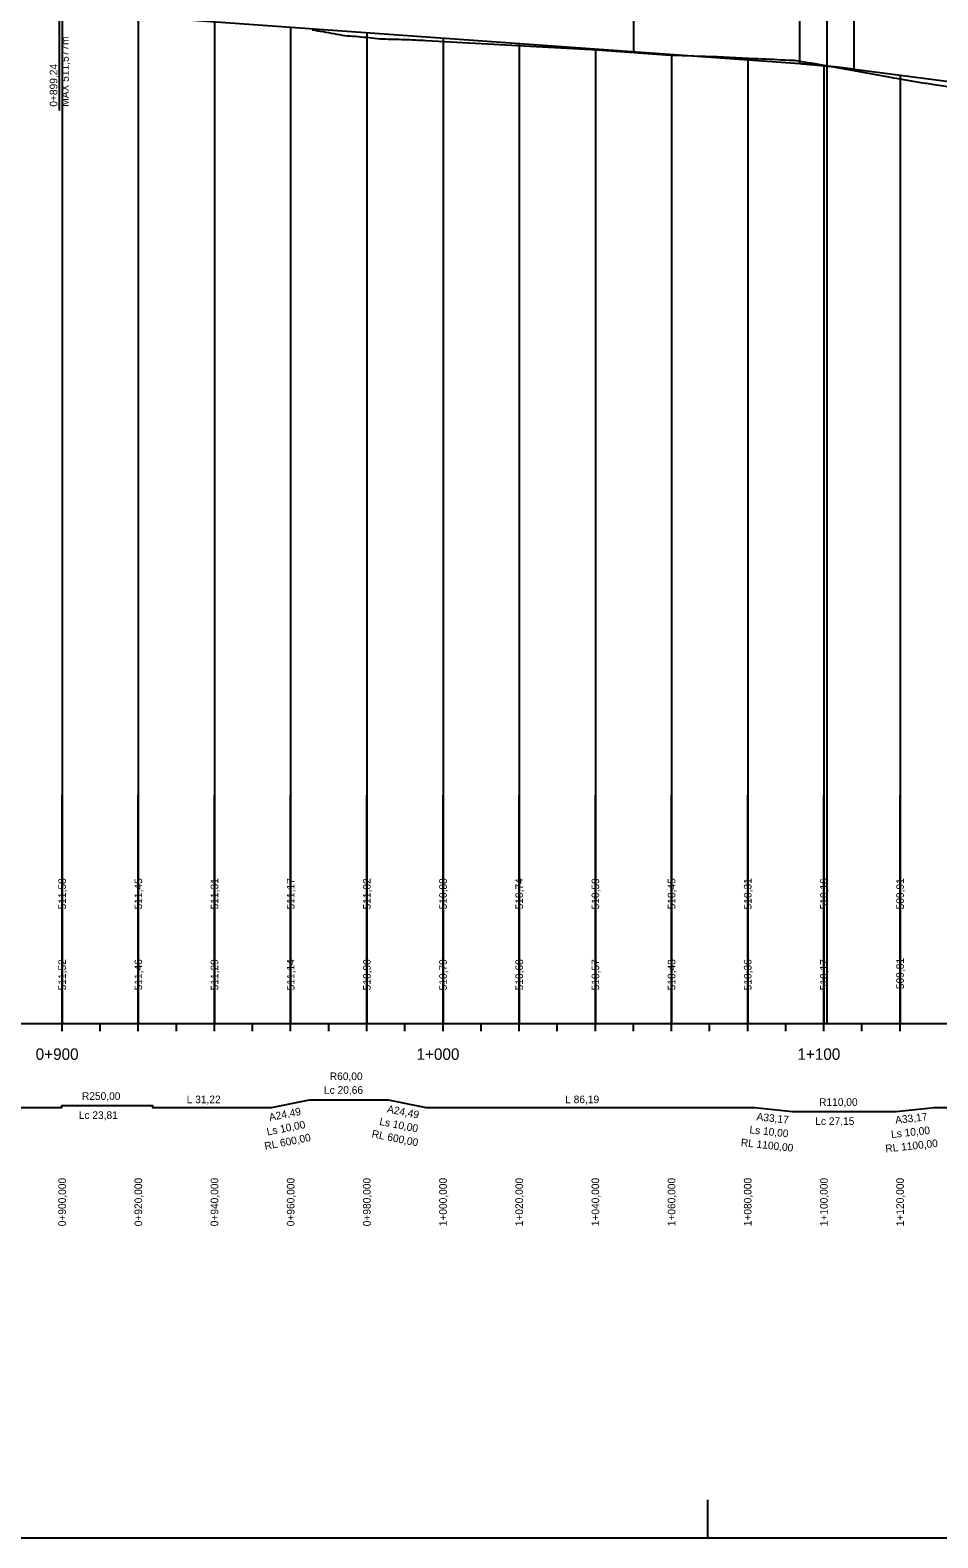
# Model space of a CAD drawing. Extents: x -632716 to -629545, y -1094726 to -1088285.
# Drawn here: x -631637 to -631398.7, y -1091981 to -1091585.1 of the extents above; entities that cross this region are included whole.
import ezdxf

# ---------------------------------------------------------------- set-up
doc = ezdxf.new("R2010")
doc.units = 0
for name, color, linetype in [('20', 7, 'Continuous'), ('Default', 7, 'Continuous'), ('formát', 7, 'Continuous'), ('NIVELETA_VYSKY', 7, 'Continuous'), ('REZ_POPIS', 7, 'Continuous'), ('REZ_TABULKA', 7, 'Continuous'), ('REZ_TENKA', 7, 'Continuous'), ('REZ_TLUSTA', 7, 'Continuous'), ('SKLONY_NIVELETA', 7, 'Continuous'), ('SKLONY_POPIS', 7, 'Continuous'), ('TECNY_NIVELETA', 7, 'Continuous'), ('TEREN_VYSKY', 7, 'Continuous'), ('VOZOVKA', 7, 'Continuous')]:
    doc.layers.add(name, color=color, linetype=linetype)

msp = doc.modelspace()

# ---------------------------------------------------------------- linework, layer by layer
at = {"layer": '20'}
for points in [[(-631628.64, -1091580.23), (-631628.64, -1091795.99), (-631628.64, -1091845.99), (-631628.64, -1091785.99)], [(-631608.64, -1091581.46), (-631608.64, -1091795.99), (-631608.64, -1091845.99), (-631608.64, -1091785.99)], [(-631588.64, -1091582.89), (-631588.64, -1091795.99), (-631588.64, -1091845.99), (-631588.64, -1091785.99)], [(-631568.64, -1091584.32), (-631568.64, -1091795.99), (-631568.64, -1091845.99), (-631568.64, -1091785.99)], [(-631548.64, -1091585.76), (-631548.64, -1091795.99), (-631548.64, -1091845.99), (-631548.64, -1091785.99)], [(-631528.64, -1091587.19), (-631528.64, -1091795.99), (-631528.64, -1091845.99), (-631528.64, -1091785.99)], [(-631508.64, -1091588.62), (-631508.64, -1091795.99), (-631508.64, -1091845.99), (-631508.64, -1091785.99)], [(-631488.64, -1091590.05), (-631488.64, -1091795.99), (-631488.64, -1091845.99), (-631488.64, -1091785.99)], [(-631468.64, -1091591.48), (-631468.64, -1091795.99), (-631468.64, -1091845.99), (-631468.64, -1091785.99)], [(-631448.64, -1091592.91), (-631448.64, -1091795.99), (-631448.64, -1091845.99), (-631448.64, -1091785.99)], [(-631428.64, -1091594.43), (-631428.64, -1091795.99), (-631428.64, -1091845.99), (-631428.64, -1091785.99)], [(-631408.64, -1091596.9), (-631408.64, -1091795.99), (-631408.64, -1091845.99), (-631408.64, -1091785.99)]]:
    msp.add_lwpolyline(points, dxfattribs=at)
at = {"layer": 'Default'}
for p, q in [((-631622.48, -1091580.47), (-631434.99, -1091593.89)), ((-631420.67, -1091595.33), (-631303.16, -1091610.61))]:
    msp.add_line(p, q, dxfattribs=at)
msp.add_lwpolyline([(-631434.99, -1091593.89), (-631434.69, -1091593.91), (-631434.39, -1091593.93), (-631434.1, -1091593.96), (-631433.8, -1091593.98), (-631433.5, -1091594), (-631433.2, -1091594.03), (-631432.9, -1091594.05), (-631432.6, -1091594.07), (-631432.3, -1091594.1), (-631432.01, -1091594.12), (-631431.71, -1091594.15), (-631431.41, -1091594.17), (-631431.11, -1091594.2), (-631430.81, -1091594.23), (-631430.51, -1091594.25), (-631430.22, -1091594.28), (-631429.92, -1091594.31), (-631429.62, -1091594.33), (-631429.32, -1091594.36), (-631429.02, -1091594.39), (-631428.72, -1091594.42), (-631428.43, -1091594.45), (-631428.13, -1091594.48), (-631427.53, -1091594.54), (-631427.23, -1091594.57), (-631426.93, -1091594.6), (-631426.64, -1091594.63), (-631426.34, -1091594.66), (-631426.04, -1091594.7), (-631425.74, -1091594.73), (-631425.44, -1091594.76), (-631425.14, -1091594.79), (-631424.85, -1091594.83), (-631424.55, -1091594.86), (-631424.25, -1091594.9), (-631423.95, -1091594.93), (-631423.65, -1091594.96), (-631423.35, -1091595), (-631423.06, -1091595.04), (-631422.76, -1091595.07), (-631422.46, -1091595.11), (-631422.16, -1091595.15), (-631421.86, -1091595.18), (-631421.56, -1091595.22), (-631421.27, -1091595.26), (-631420.97, -1091595.3), (-631420.67, -1091595.33)], dxfattribs=at)
at = {"layer": 'formát'}
msp.add_line((-631459.11, -1091981.01), (-631459.11, -1091971.01), dxfattribs=at)
msp.add_lwpolyline([(-632628.81, -1091981.01), (-629779.11, -1091981.01), (-629779.11, -1091387.01), (-632628.81, -1091387.01)], close=True, dxfattribs=at)
at = {"layer": 'REZ_TABULKA'}
msp.add_lwpolyline([(-631671.12, -1091867.99), (-631628.72, -1091867.99), (-631628.72, -1091867.51), (-631604.92, -1091867.51), (-631604.92, -1091867.99), (-631573.7, -1091867.99), (-631573.7, -1091867.99), (-631563.7, -1091865.99), (-631563.7, -1091865.99), (-631543.04, -1091865.99), (-631543.04, -1091865.99), (-631533.04, -1091867.99), (-631533.04, -1091867.99), (-631446.85, -1091867.99), (-631446.85, -1091867.99), (-631436.85, -1091869.08), (-631436.85, -1091869.08), (-631409.7, -1091869.08), (-631409.7, -1091869.08), (-631399.7, -1091867.99), (-631399.7, -1091867.99), (-631332.53, -1091867.99)], dxfattribs=at)
at = {"layer": 'REZ_TENKA'}
for p, q in [((-631618.64, -1091847.99), (-631618.64, -1091845.99)), ((-631608.64, -1091847.99), (-631608.64, -1091845.99)), ((-631598.64, -1091847.99), (-631598.64, -1091845.99)), ((-631588.64, -1091847.99), (-631588.64, -1091845.99)), ((-631578.64, -1091847.99), (-631578.64, -1091845.99)), ((-631568.64, -1091847.99), (-631568.64, -1091845.99)), ((-631558.64, -1091847.99), (-631558.64, -1091845.99)), ((-631548.64, -1091847.99), (-631548.64, -1091845.99)), ((-631538.64, -1091847.99), (-631538.64, -1091845.99)), ((-631518.64, -1091847.99), (-631518.64, -1091845.99)), ((-631508.64, -1091847.99), (-631508.64, -1091845.99)), ((-631498.64, -1091847.99), (-631498.64, -1091845.99)), ((-631488.64, -1091847.99), (-631488.64, -1091845.99)), ((-631478.64, -1091847.99), (-631478.64, -1091845.99)), ((-631468.64, -1091847.99), (-631468.64, -1091845.99)), ((-631458.64, -1091847.99), (-631458.64, -1091845.99)), ((-631448.64, -1091847.99), (-631448.64, -1091845.99)), ((-631438.64, -1091847.99), (-631438.64, -1091845.99)), ((-631418.64, -1091847.99), (-631418.64, -1091845.99)), ((-631408.64, -1091847.99), (-631408.64, -1091845.99))]:
    msp.add_line(p, q, dxfattribs=at)
at = {"layer": 'REZ_TLUSTA'}
for p, q in [((-631628.64, -1091847.99), (-631628.64, -1091843.99)), ((-631528.64, -1091847.99), (-631528.64, -1091843.99)), ((-631428.64, -1091847.99), (-631428.64, -1091843.99)), ((-632528.64, -1091845.99), (-630208.64, -1091845.99))]:
    msp.add_line(p, q, dxfattribs=at)
at = {"layer": 'SKLONY_NIVELETA'}
for p, q in [((-631478.64, -1091431.37), (-631478.64, -1091590.77)), ((-631427.83, -1091494.4), (-631427.83, -1091845.99)), ((-631622.48, -1091580.47), (-631434.99, -1091593.89)), ((-631420.67, -1091595.33), (-631303.16, -1091610.61))]:
    msp.add_line(p, q, dxfattribs=at)
msp.add_lwpolyline([(-631434.99, -1091593.89), (-631434.69, -1091593.91), (-631434.39, -1091593.93), (-631434.1, -1091593.96), (-631433.8, -1091593.98), (-631433.5, -1091594), (-631433.2, -1091594.03), (-631432.9, -1091594.05), (-631432.6, -1091594.07), (-631432.3, -1091594.1), (-631432.01, -1091594.12), (-631431.71, -1091594.15), (-631431.41, -1091594.17), (-631431.11, -1091594.2), (-631430.81, -1091594.23), (-631430.51, -1091594.25), (-631430.22, -1091594.28), (-631429.92, -1091594.31), (-631429.62, -1091594.33), (-631429.32, -1091594.36), (-631429.02, -1091594.39), (-631428.72, -1091594.42), (-631428.43, -1091594.45), (-631428.13, -1091594.48), (-631427.53, -1091594.54), (-631427.23, -1091594.57), (-631426.93, -1091594.6), (-631426.64, -1091594.63), (-631426.34, -1091594.66), (-631426.04, -1091594.7), (-631425.74, -1091594.73), (-631425.44, -1091594.76), (-631425.14, -1091594.79), (-631424.85, -1091594.83), (-631424.55, -1091594.86), (-631424.25, -1091594.9), (-631423.95, -1091594.93), (-631423.65, -1091594.96), (-631423.35, -1091595), (-631423.06, -1091595.04), (-631422.76, -1091595.07), (-631422.46, -1091595.11), (-631422.16, -1091595.15), (-631421.86, -1091595.18), (-631421.56, -1091595.22), (-631421.27, -1091595.26), (-631420.97, -1091595.3), (-631420.67, -1091595.33)], dxfattribs=at)
at = {"layer": 'TECNY_NIVELETA'}
for p, q in [((-631434.99, -1091593.89), (-631434.99, -1091492.89)), ((-631420.67, -1091595.33), (-631420.67, -1091494.33)), ((-631629.39, -1091580.22), (-631629.39, -1091606.22))]:
    msp.add_line(p, q, dxfattribs=at)
at = {"layer": 'VOZOVKA'}
msp.add_lwpolyline([(-631562.99, -1091585.04), (-631562.27, -1091585.15), (-631561.56, -1091585.26), (-631560.85, -1091585.38), (-631560.14, -1091585.5), (-631559.42, -1091585.62), (-631558.71, -1091585.74), (-631558, -1091585.87), (-631557.29, -1091586.01), (-631556.58, -1091586.14), (-631555.86, -1091586.28), (-631555.15, -1091586.42), (-631554.7, -1091586.52), (-631554.44, -1091586.53), (-631553.73, -1091586.58), (-631553.01, -1091586.63), (-631552.3, -1091586.68), (-631551.59, -1091586.74), (-631550.88, -1091586.8), (-631550.16, -1091586.86), (-631549.45, -1091586.93), (-631548.74, -1091587), (-631548.03, -1091587.07), (-631547.31, -1091587.15), (-631546.6, -1091587.23), (-631545.89, -1091587.32), (-631545.27, -1091587.4), (-631545.18, -1091587.4), (-631544.47, -1091587.42), (-631543.75, -1091587.43), (-631543.04, -1091587.45), (-631542.33, -1091587.47), (-631541.61, -1091587.49), (-631540.9, -1091587.5), (-631540.18, -1091587.52), (-631539.47, -1091587.54), (-631538.75, -1091587.56), (-631538.04, -1091587.57), (-631537.44, -1091587.59), (-631537.33, -1091587.59), (-631536.61, -1091587.63), (-631535.9, -1091587.67), (-631535.18, -1091587.71), (-631534.47, -1091587.75), (-631533.75, -1091587.79), (-631533.04, -1091587.83), (-631488.1, -1091590.33), (-631468.9, -1091591.68), (-631456.65, -1091592.03), (-631446.85, -1091592.52), (-631445.85, -1091592.57), (-631444.85, -1091592.62), (-631443.85, -1091592.67), (-631442.85, -1091592.72), (-631441.85, -1091592.77), (-631440.85, -1091592.82), (-631439.85, -1091592.87), (-631438.85, -1091592.92), (-631437.85, -1091592.97), (-631436.85, -1091593.02), (-631436.41, -1091593.04), (-631435.88, -1091593.13), (-631434.91, -1091593.28), (-631433.94, -1091593.43), (-631432.97, -1091593.58), (-631432, -1091593.73), (-631431.03, -1091593.88), (-631430.57, -1091593.95), (-631430.06, -1091594.04), (-631429.09, -1091594.21), (-631428.12, -1091594.39), (-631427.15, -1091594.56), (-631426.18, -1091594.73), (-631425.21, -1091594.9), (-631424.24, -1091595.07), (-631423.67, -1091595.17), (-631423.27, -1091595.25), (-631422.3, -1091595.43), (-631421.33, -1091595.62), (-631420.36, -1091595.8), (-631419.39, -1091595.98), (-631418.42, -1091596.16), (-631417.45, -1091596.34), (-631416.49, -1091596.52), (-631415.52, -1091596.7), (-631414.55, -1091596.88), (-631413.58, -1091597.06), (-631412.61, -1091597.23), (-631411.64, -1091597.41), (-631410.67, -1091597.59), (-631410.45, -1091597.62), (-631409.7, -1091597.75), (-631408.7, -1091597.91), (-631407.7, -1091598.08), (-631406.7, -1091598.24), (-631405.7, -1091598.41), (-631404.7, -1091598.58), (-631403.7, -1091598.75), (-631402.7, -1091598.92), (-631401.94, -1091599.04), (-631401.7, -1091599.08), (-631400.7, -1091599.22), (-631399.7, -1091599.37), (-631361.71, -1091604.91)], dxfattribs=at)

# ---------------------------------------------------------------- texts
at = {"layer": 'NIVELETA_VYSKY'}
for s, p in [('511,58', (-631627.64, -1091815.99)), ('511,45', (-631607.64, -1091815.99)), ('511,31', (-631587.64, -1091815.99)), ('511,17', (-631567.64, -1091815.99)), ('511,02', (-631547.64, -1091815.99)), ('510,88', (-631527.64, -1091815.99)), ('510,74', (-631507.64, -1091815.99)), ('510,59', (-631487.64, -1091815.99)), ('510,45', (-631467.64, -1091815.99)), ('510,31', (-631447.64, -1091815.99)), ('510,16', (-631427.64, -1091815.99)), ('509,91', (-631407.64, -1091815.99))]:
    msp.add_text(s, height=2, rotation=90, dxfattribs=at).set_placement(p)
at = {"layer": 'REZ_POPIS'}
for s, p in [('0+900', (-631635.59, -1091855.49)), ('1+000', (-631535.59, -1091855.49)), ('1+100', (-631435.59, -1091855.49))]:
    msp.add_text(s, height=3, dxfattribs=at).set_placement(p)
at = {"layer": 'REZ_TABULKA'}
for s, p in [('R60,00', (-631558.37, -1091860.81)), ('R250,00', (-631623.44, -1091866.01)), ('Lc 20,66', (-631559.89, -1091864.41)), ('L 31,22', (-631595.94, -1091866.88)), ('L 86,19', (-631496.57, -1091866.88)), ('R110,00', (-631429.89, -1091867.58)), ('Lc 23,81', (-631624.28, -1091871.01)), ('Lc 27,15', (-631430.89, -1091872.58))]:
    msp.add_text(s, height=2, dxfattribs=at).set_placement(p)
for s, rotation, p in [('A24,49', 11.3099, (-631574.11, -1091871.59)), ('A24,49', 348.6901, (-631543.45, -1091869.28)), ('Ls 10,00', 11.3099, (-631574.71, -1091875.38)), ('Ls 10,00', 348.6901, (-631545.46, -1091872.55)), ('A33,17', 353.7742, (-631446.39, -1091871.34)), ('A33,17', 6.2258, (-631409.81, -1091872.3)), ('RL 600,00', 11.3099, (-631575.31, -1091879.17)), ('RL 600,00', 348.6901, (-631547.48, -1091875.82)), ('RL 1100,00', 353.7742, (-631450.53, -1091878.13)), ('Ls 10,00', 353.7742, (-631448.25, -1091874.76)), ('Ls 10,00', 6.2258, (-631410.89, -1091876.04)), ('RL 1100,00', 6.2258, (-631412.39, -1091879.82)), ('0+900,000', 90, (-631627.64, -1091899.2)), ('0+920,000', 90, (-631607.64, -1091899.2)), ('0+940,000', 90, (-631587.64, -1091899.2)), ('0+960,000', 90, (-631567.64, -1091899.2)), ('0+980,000', 90, (-631547.64, -1091899.2)), ('1+000,000', 90, (-631527.64, -1091899.2)), ('1+020,000', 90, (-631507.64, -1091899.2)), ('1+040,000', 90, (-631487.64, -1091899.2)), ('1+060,000', 90, (-631467.64, -1091899.2)), ('1+080,000', 90, (-631447.64, -1091899.2)), ('1+100,000', 90, (-631427.64, -1091899.2)), ('1+120,000', 90, (-631407.64, -1091899.2))]:
    msp.add_text(s, height=2, rotation=rotation, dxfattribs=at).set_placement(p)
at = {"layer": 'SKLONY_POPIS'}
for s, p in [('MAX 511,577m', (-631626.89, -1091605.22)), ('0+899,24', (-631629.89, -1091605.22))]:
    msp.add_text(s, height=2, rotation=90, dxfattribs=at).set_placement(p)
at = {"layer": 'TEREN_VYSKY'}
for s, p in [('511,52', (-631627.64, -1091837.25)), ('511,46', (-631607.64, -1091837.25)), ('511,29', (-631587.64, -1091837.25)), ('511,14', (-631567.64, -1091837.25)), ('510,90', (-631547.64, -1091837.25)), ('510,79', (-631527.64, -1091837.25)), ('510,68', (-631507.64, -1091837.25)), ('510,57', (-631487.64, -1091837.25)), ('510,43', (-631467.64, -1091837.25)), ('510,36', (-631447.64, -1091837.25)), ('510,17', (-631427.64, -1091837.25)), ('509,81', (-631407.64, -1091836.92))]:
    msp.add_text(s, height=2, rotation=90, dxfattribs=at).set_placement(p)

doc.saveas('drawing.dxf')
